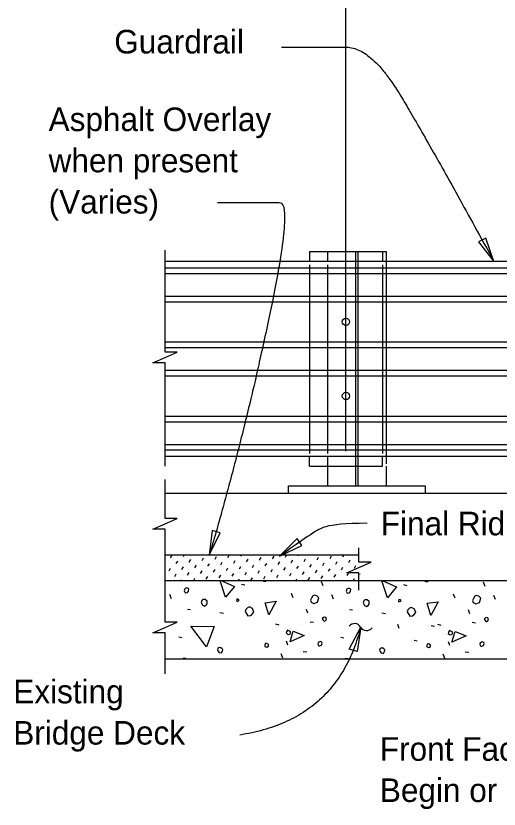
# Model space of a CAD drawing. Extents: x 21587 to 21656.3, y 56114 to 56157.2.
# Drawn here: x 21606.04 to 21610.17, y 56132.1 to 56138.88 of the extents above; entities that cross this region are included whole.
import ezdxf

# ---------------------------------------------------------------- set-up
doc = ezdxf.new("R2010")
doc.units = 0
for name, color, linetype in [('AdhocPoint_dp', 7, 'Continuous'), ('Border', 7, 'Continuous'), ('Patterning', 7, 'Continuous'), ('PlotBorder_dp', 7, 'Continuous'), ('SheetBorder_dp', 7, 'Continuous'), ('TextMisc', 7, 'Continuous')]:
    doc.layers.add(name, color=color, linetype=linetype)

msp = doc.modelspace()

# ---------------------------------------------------------------- linework, layer by layer
at = {"layer": 'AdhocPoint_dp'}
for p, q in [((21607.3117, 56134.8009), (21613.4854, 56134.8009)), ((21608.9696, 56134.2699), (21607.3116, 56134.2699)), ((21613.4854, 56134.0509), (21607.3117, 56134.0509)), ((21607.3117, 56133.3843), (21613.4854, 56133.3843))]:
    msp.add_line(p, q, dxfattribs=at)
at = {"layer": 'Border'}
for p, q in [((21608.7018, 56136.8635), (21609.2018, 56136.8635)), ((21608.7018, 56136.8635), (21608.7018, 56136.7802)), ((21619.5663, 56136.7801), (21607.3117, 56136.7801)), ((21607.3117, 56136.7246), (21619.5663, 56136.7246)), ((21607.3117, 56136.6764), (21619.5663, 56136.6764)), ((21607.3117, 56136.4835), (21619.5663, 56136.4835)), ((21607.3117, 56136.4353), (21619.5663, 56136.4353)), ((21607.3117, 56136.0914), (21619.5663, 56136.0914)), ((21607.3117, 56136.0431), (21619.5663, 56136.0431)), ((21607.3117, 56135.8503), (21619.5663, 56135.8503)), ((21607.3117, 56135.8022), (21619.5663, 56135.8022)), ((21607.3117, 56135.4582), (21619.5663, 56135.4582)), ((21607.3117, 56135.41), (21619.5663, 56135.41)), ((21607.3117, 56135.2172), (21619.5663, 56135.2172)), ((21607.3117, 56135.169), (21619.5663, 56135.169)), ((21619.5663, 56135.1134), (21607.3117, 56135.1134)), ((21608.7018, 56135.1135), (21608.7018, 56134.8635)), ((21609.2018, 56135.0302), (21609.2018, 56134.8635)), ((21608.3685, 56134.8635), (21609.5351, 56134.8635)), ((21608.3685, 56134.801), (21608.3685, 56134.8635)), ((21608.7018, 56134.8635), (21609.2018, 56134.8635)), ((21609.5351, 56134.8635), (21609.5351, 56134.801)), ((21608.3685, 56134.801), (21609.5351, 56134.801))]:
    msp.add_line(p, q, dxfattribs=at)
for centre in [(21608.858, 56136.2634), (21608.858, 56135.6303)]:
    msp.add_circle(centre, 0.0312, dxfattribs=at)
at = {"layer": 'Patterning'}
for p, q in [((21608.9414, 56134.8635), (21608.9414, 56136.8635)), ((21608.9622, 56134.8635), (21608.9622, 56136.8635)), ((21609.2018, 56136.8635), (21609.2018, 56135.0505)), ((21608.7018, 56136.7516), (21608.7018, 56135.1398))]:
    msp.add_line(p, q, dxfattribs=at)
at = {"layer": 'PlotBorder_dp'}
msp.add_line((21608.858, 56135.1577), (21608.858, 56143.2258), dxfattribs=at)
for points in [[(21610.1227, 56136.7797), (21610.0537, 56136.9793), (21609.9918, 56136.9455)], [(21607.6902, 56134.2707), (21607.7828, 56134.4606), (21607.7151, 56134.4805)], [(21608.2911, 56134.2633), (21608.4817, 56134.3543), (21608.4411, 56134.412)], [(21608.9843, 56133.6565), (21608.9539, 56133.4475), (21608.8867, 56133.4692)]]:
    msp.add_lwpolyline(points, close=True, dxfattribs=at)
for points in [[(21607.3117, 56135.0303), (21607.3117, 56135.9135), (21607.2084, 56135.9135), (21607.3117, 56135.9585), (21607.4151, 56136.0035), (21607.3117, 56136.0035), (21607.3117, 56136.8765)], [(21607.3117, 56134.0229), (21607.3117, 56134.493), (21607.2084, 56134.493), (21607.3117, 56134.538), (21607.4151, 56134.583), (21607.3117, 56134.583), (21607.3117, 56134.9175)], [(21608.9697, 56133.972), (21608.9697, 56134.1198), (21608.8664, 56134.1198), (21608.9697, 56134.1648), (21609.073, 56134.2098), (21608.9697, 56134.2098), (21608.9697, 56134.3343)], [(21607.3117, 56133.2578), (21607.3117, 56133.6084), (21607.2084, 56133.6084), (21607.3117, 56133.6534), (21607.4151, 56133.6984), (21607.3117, 56133.6984), (21607.3117, 56134.0229)]]:
    msp.add_lwpolyline(points, dxfattribs=at)
for centre, start, end in [((21608.9319, 56133.6269), 30.00813, 141.73535), ((21609.0352, 56133.6865), 210.00813, 321.73535)]:
    msp.add_arc(centre, 0.0596, start, end, dxfattribs=at)
for points, degree in [([(21608.3061, 56138.6093), (21608.6424, 56138.6093), (21609.0737, 56138.6093), (21609.5653, 56137.7986), (21610.1227, 56136.7797)], 2), ([(21607.7603, 56137.2827), (21608.1708, 56137.2827), (21608.4111, 56137.2827), (21607.9729, 56135.2323), (21607.6902, 56134.2708)], 2), ([(21609.0397, 56134.5436), (21608.8463, 56134.5415), (21608.6579, 56134.5211), (21608.5865, 56134.4713), (21608.2911, 56134.2634)], 3), ([(21608.9843, 56133.6565), (21608.7837, 56132.8621), (21607.9506, 56132.735)], 2)]:
    msp.add_open_spline(points, degree=degree, dxfattribs=at)
at = {"layer": 'TextMisc'}
for p, q in [((21608.5455, 56136.8635), (21609.1705, 56136.8635)), ((21608.5455, 56136.8635), (21608.5455, 56136.7802)), ((21609.1705, 56136.8635), (21609.1705, 56136.7802)), ((21608.5455, 56136.7516), (21608.5455, 56135.1398)), ((21609.1705, 56136.7516), (21609.1705, 56135.1398)), ((21608.5455, 56135.0302), (21608.5455, 56135.1135)), ((21609.1705, 56135.0302), (21609.1705, 56135.1135)), ((21608.5455, 56135.0302), (21609.1705, 56135.0302)), ((21607.3586, 56134.2474), (21607.3715, 56134.2698)), ((21607.4692, 56134.2604), (21607.4747, 56134.2699)), ((21607.6287, 56134.2245), (21607.6416, 56134.2469)), ((21607.7393, 56134.2375), (21607.7523, 56134.2599)), ((21607.8499, 56134.2504), (21607.8612, 56134.2699)), ((21607.9606, 56134.2634), (21607.9643, 56134.2699)), ((21608.0094, 56134.2146), (21608.0224, 56134.237)), ((21608.12, 56134.2275), (21608.133, 56134.2499)), ((21608.2307, 56134.2405), (21608.2436, 56134.2629)), ((21608.3413, 56134.2535), (21608.3508, 56134.2699)), ((21608.4519, 56134.2664), (21608.4539, 56134.2699)), ((21608.5008, 56134.2176), (21608.5137, 56134.24)), ((21608.6114, 56134.2306), (21608.6244, 56134.253)), ((21608.722, 56134.2435), (21608.735, 56134.2659)), ((21608.8327, 56134.2565), (21608.8404, 56134.2699)), ((21608.9433, 56134.2695), (21608.9436, 56134.2699)), ((21607.4074, 56134.1986), (21607.4204, 56134.221)), ((21607.4562, 56134.1498), (21607.4692, 56134.1722)), ((21607.518, 56134.2116), (21607.531, 56134.234)), ((21607.5669, 56134.1627), (21607.5798, 56134.1851)), ((21607.6775, 56134.1757), (21607.6905, 56134.1981)), ((21607.7881, 56134.1887), (21607.8011, 56134.211)), ((21607.8988, 56134.2016), (21607.9117, 56134.224)), ((21607.9476, 56134.1528), (21607.9606, 56134.1752)), ((21608.0582, 56134.1657), (21608.0712, 56134.1881)), ((21608.1689, 56134.1787), (21608.1818, 56134.2011)), ((21608.2795, 56134.1917), (21608.2925, 56134.2141)), ((21608.3901, 56134.2046), (21608.4031, 56134.227)), ((21608.439, 56134.1558), (21608.4519, 56134.1782)), ((21608.5496, 56134.1688), (21608.5626, 56134.1912)), ((21608.6602, 56134.1817), (21608.6732, 56134.2041)), ((21608.7709, 56134.1947), (21608.7838, 56134.2171)), ((21608.8197, 56134.1459), (21608.8327, 56134.1682)), ((21608.8815, 56134.2077), (21608.8945, 56134.23)), ((21608.9303, 56134.1588), (21608.9433, 56134.1812)), ((21607.3456, 56134.1368), (21607.3586, 56134.1592)), ((21607.3944, 56134.088), (21607.4074, 56134.1104)), ((21607.5051, 56134.1009), (21607.518, 56134.1233)), ((21607.6157, 56134.1139), (21607.6287, 56134.1363)), ((21607.7263, 56134.1269), (21607.7393, 56134.1492)), ((21607.7752, 56134.078), (21607.7881, 56134.1004)), ((21607.837, 56134.1398), (21607.8499, 56134.1622)), ((21607.8858, 56134.091), (21607.8988, 56134.1134)), ((21607.9964, 56134.1039), (21608.0094, 56134.1263)), ((21608.1071, 56134.1169), (21608.12, 56134.1393)), ((21608.2177, 56134.1299), (21608.2307, 56134.1523)), ((21608.2665, 56134.081), (21608.2795, 56134.1034)), ((21608.3283, 56134.1428), (21608.3413, 56134.1652)), ((21608.3772, 56134.094), (21608.3901, 56134.1164)), ((21608.4878, 56134.107), (21608.5008, 56134.1294)), ((21608.5984, 56134.1199), (21608.6114, 56134.1423)), ((21608.7091, 56134.1329), (21608.722, 56134.1553)), ((21608.7579, 56134.0841), (21608.7709, 56134.1065)), ((21608.8685, 56134.097), (21608.8815, 56134.1194)), ((21608.9792, 56134.11), (21608.9793, 56134.1102)), ((21607.4501, 56134.0509), (21607.4562, 56134.0615)), ((21607.5539, 56134.0521), (21607.5669, 56134.0745)), ((21607.6645, 56134.0651), (21607.6775, 56134.0874)), ((21607.8366, 56134.0509), (21607.837, 56134.0516)), ((21607.9397, 56134.0509), (21607.9476, 56134.0645)), ((21608.0453, 56134.0551), (21608.0582, 56134.0775)), ((21608.1559, 56134.0681), (21608.1689, 56134.0905)), ((21608.3262, 56134.0509), (21608.3283, 56134.0546)), ((21608.4293, 56134.0509), (21608.439, 56134.0676)), ((21608.5366, 56134.0581), (21608.5496, 56134.0805)), ((21608.6473, 56134.0711), (21608.6602, 56134.0935)), ((21608.6635, 56134.0079), (21608.6494, 56134.0432)), ((21608.8158, 56134.0509), (21608.8197, 56134.0576)), ((21608.919, 56134.0509), (21608.9303, 56134.0706)), ((21610.0482, 56134.0043), (21610.034, 56134.0397)), ((21607.9652, 56134.0238), (21607.9935, 56134.0167)), ((21609.3499, 56134.0203), (21609.3782, 56134.0132)), ((21607.3666, 56133.8989), (21607.3524, 56133.9343)), ((21608.4072, 56133.9071), (21608.393, 56133.9425)), ((21608.7513, 56133.8954), (21608.7371, 56133.9307)), ((21609.7919, 56133.9036), (21609.7777, 56133.9389)), ((21610.1359, 56133.8918), (21610.1218, 56133.9272)), ((21607.5045, 56133.8105), (21607.5292, 56133.807)), ((21607.7802, 56133.7822), (21607.8103, 56133.7769)), ((21608.5327, 56133.7745), (21608.5203, 56133.8081)), ((21608.8892, 56133.807), (21608.9139, 56133.8034)), ((21609.1649, 56133.7787), (21609.195, 56133.7734)), ((21609.9174, 56133.771), (21609.905, 56133.8046)), ((21608.5515, 56133.7027), (21608.5816, 56133.6974)), ((21609.9362, 56133.6991), (21609.9662, 56133.6938)), ((21608.2552, 56133.6844), (21608.2834, 56133.6773)), ((21609.3134, 56133.6443), (21609.301, 56133.6779)), ((21609.5874, 56133.6709), (21609.6157, 56133.6638)), ((21609.6398, 56133.6808), (21609.6681, 56133.6738)), ((21607.4302, 56133.5736), (21607.4567, 56133.5683)), ((21608.8149, 56133.5701), (21608.8414, 56133.5648)), ((21608.3612, 56133.5018), (21608.3488, 56133.5354)), ((21609.4407, 56133.5453), (21609.4672, 56133.54)), ((21609.7459, 56133.4982), (21609.7335, 56133.5318)), ((21608.3188, 56133.3922), (21608.3046, 56133.4275)), ((21608.4914, 56133.4481), (21608.5232, 56133.4446)), ((21609.7035, 56133.3886), (21609.6893, 56133.424)), ((21609.8761, 56133.4446), (21609.9079, 56133.4411))]:
    msp.add_line(p, q, dxfattribs=at)
for points in [[(21607.828, 56133.9113), (21607.7825, 56134.0509)], [(21607.7964, 56134.0509), (21607.9058, 56134.0032), (21607.828, 56133.9113)], [(21608.1516, 56134.0509), (21608.1526, 56134.0485), (21608.1502, 56134.0509)], [(21608.1526, 56134.0485), (21608.1738, 56134.0485), (21608.1762, 56134.0509)], [(21609.2127, 56133.9077), (21609.1661, 56134.0509)], [(21609.173, 56134.0509), (21609.2904, 56133.9997), (21609.2127, 56133.9077)], [(21609.5348, 56134.0509), (21609.5373, 56134.045), (21609.5338, 56134.0485)], [(21609.5373, 56134.045), (21609.5585, 56134.045), (21609.5644, 56134.0509)], [(21607.4762, 56133.9661), (21607.485, 56133.9502), (21607.5045, 56133.9519), (21607.5133, 56133.9643), (21607.5151, 56133.9838), (21607.5027, 56133.9891), (21607.4939, 56133.9908), (21607.4833, 56133.9873), (21607.4797, 56133.9838), (21607.4762, 56133.9661)], [(21608.8609, 56133.9625), (21608.8697, 56133.9466), (21608.8892, 56133.9484), (21608.898, 56133.9608), (21608.8998, 56133.9802), (21608.8874, 56133.9855), (21608.8785, 56133.9873), (21608.8679, 56133.9838), (21608.8644, 56133.9802), (21608.8609, 56133.9625)], [(21607.927, 56133.8759), (21607.9464, 56133.8848), (21607.9393, 56133.8918), (21607.927, 56133.8971), (21607.9217, 56133.8848), (21607.927, 56133.8759)], [(21608.561, 56133.87), (21608.584, 56133.8576), (21608.614, 56133.87), (21608.6264, 56133.9071), (21608.6087, 56133.9248), (21608.5857, 56133.9301), (21608.5751, 56133.923), (21608.5627, 56133.9036), (21608.5539, 56133.8877), (21608.561, 56133.87)], [(21609.9457, 56133.8665), (21609.9686, 56133.8541), (21609.9987, 56133.8665), (21610.0111, 56133.9036), (21609.9934, 56133.9213), (21609.9704, 56133.9266), (21609.9598, 56133.9195), (21609.9474, 56133.9), (21609.9386, 56133.8841), (21609.9457, 56133.8665)], [(21607.6211, 56133.8671), (21607.6318, 56133.8459), (21607.6494, 56133.8353), (21607.6636, 56133.8459), (21607.6706, 56133.8565), (21607.6706, 56133.8777), (21607.6547, 56133.8936), (21607.6353, 56133.8918), (21607.6265, 56133.883), (21607.6211, 56133.8671)], [(21608.2003, 56133.7604), (21608.1668, 56133.8647), (21608.2605, 56133.8771), (21608.2003, 56133.7604)], [(21609.0058, 56133.8635), (21609.0164, 56133.8423), (21609.0341, 56133.8317), (21609.0483, 56133.8423), (21609.0553, 56133.8529), (21609.0553, 56133.8742), (21609.0394, 56133.8901), (21609.02, 56133.8883), (21609.0111, 56133.8795), (21609.0058, 56133.8635)], [(21609.3116, 56133.8724), (21609.3311, 56133.8812), (21609.324, 56133.8883), (21609.3116, 56133.8936), (21609.3063, 56133.8812), (21609.3116, 56133.8724)], [(21609.585, 56133.7569), (21609.5514, 56133.8612), (21609.6451, 56133.8735), (21609.585, 56133.7569)], [(21607.9977, 56133.7911), (21608.0207, 56133.7539), (21608.0436, 56133.7557), (21608.0525, 56133.7646), (21608.0719, 56133.784), (21608.0596, 56133.814), (21608.0348, 56133.8282), (21608.0171, 56133.8211), (21608.003, 56133.807), (21607.9977, 56133.7911)], [(21609.3824, 56133.7875), (21609.4053, 56133.7504), (21609.4283, 56133.7522), (21609.4372, 56133.761), (21609.4566, 56133.7805), (21609.4442, 56133.8105), (21609.4195, 56133.8247), (21609.4018, 56133.8176), (21609.3877, 56133.8034), (21609.3824, 56133.7875)], [(21608.6629, 56133.7151), (21608.6735, 56133.7044), (21608.6841, 56133.7115), (21608.6912, 56133.7221), (21608.6876, 56133.7398), (21608.6788, 56133.7416), (21608.6664, 56133.7398), (21608.6558, 56133.7292), (21608.6629, 56133.7151)], [(21610.0476, 56133.7115), (21610.0582, 56133.7009), (21610.0688, 56133.708), (21610.0758, 56133.7186), (21610.0723, 56133.7363), (21610.0635, 56133.738), (21610.0511, 56133.7363), (21610.0405, 56133.7257), (21610.0476, 56133.7115)], [(21607.6653, 56133.487), (21607.531, 56133.6638), (21607.7307, 56133.662), (21607.6653, 56133.487)], [(21608.3577, 56133.596), (21608.3701, 56133.5942), (21608.3824, 56133.5995), (21608.386, 56133.6101), (21608.3807, 56133.619), (21608.3701, 56133.626), (21608.3577, 56133.6313), (21608.3506, 56133.6172), (21608.3471, 56133.6066), (21608.3577, 56133.596)], [(21609.7424, 56133.5925), (21609.7547, 56133.5907), (21609.7671, 56133.596), (21609.7706, 56133.6066), (21609.7653, 56133.6154), (21609.7547, 56133.6225), (21609.7424, 56133.6278), (21609.7353, 56133.6137), (21609.7318, 56133.6031), (21609.7424, 56133.5925)], [(21608.38, 56133.5312), (21608.4083, 56133.6231), (21608.502, 56133.586), (21608.38, 56133.5312)], [(21609.7647, 56133.5277), (21609.793, 56133.6196), (21609.8867, 56133.5825), (21609.7647, 56133.5277)], [(21608.1639, 56133.4905), (21608.1833, 56133.4852), (21608.1957, 56133.4941), (21608.1974, 56133.5065), (21608.1939, 56133.51), (21608.1798, 56133.5171), (21608.1674, 56133.5153), (21608.1656, 56133.5029), (21608.1639, 56133.4905)], [(21608.6275, 56133.4959), (21608.6346, 56133.4959), (21608.6487, 56133.5029), (21608.654, 56133.5188), (21608.6523, 56133.5277), (21608.6381, 56133.5347), (21608.6205, 56133.5241), (21608.6169, 56133.5135), (21608.6205, 56133.5029), (21608.6275, 56133.4959)], [(21609.5485, 56133.487), (21609.568, 56133.4817), (21609.5803, 56133.4905), (21609.5821, 56133.5029), (21609.5786, 56133.5065), (21609.5644, 56133.5135), (21609.5521, 56133.5118), (21609.5503, 56133.4994), (21609.5485, 56133.487)], [(21610.0122, 56133.4923), (21610.0193, 56133.4923), (21610.0334, 56133.4994), (21610.0387, 56133.5153), (21610.0369, 56133.5241), (21610.0228, 56133.5312), (21610.0051, 56133.5206), (21610.0016, 56133.51), (21610.0051, 56133.4994), (21610.0122, 56133.4923)], [(21607.7643, 56133.4552), (21607.7732, 56133.4393), (21607.7944, 56133.4357), (21607.8032, 56133.4517), (21607.8068, 56133.4658), (21607.7979, 56133.4746), (21607.782, 56133.4835), (21607.7661, 56133.4782), (21607.7608, 56133.4623), (21607.7643, 56133.4552)], [(21609.149, 56133.4517), (21609.1579, 56133.4357), (21609.1791, 56133.4322), (21609.1879, 56133.4481), (21609.1914, 56133.4623), (21609.1826, 56133.4711), (21609.1667, 56133.4799), (21609.1508, 56133.4746), (21609.1455, 56133.4587), (21609.149, 56133.4517)], [(21607.4896, 56133.3843), (21607.4886, 56133.388), (21607.4656, 56133.3898), (21607.4637, 56133.3843)], [(21608.8733, 56133.3843), (21608.8732, 56133.3845), (21608.8503, 56133.3862), (21608.8496, 56133.3843)]]:
    msp.add_lwpolyline(points, dxfattribs=at)

# ---------------------------------------------------------------- texts
at = {"layer": 'PlotBorder_dp'}
for s, p in [('Guardrail', (21606.8775, 56138.5552)), ('Asphalt Overlay', (21606.3166, 56137.8923)), ('when present', (21606.3166, 56137.5403)), ('(Varies)', (21606.3166, 56137.1883)), ('Existing ', (21606.0143, 56133.0052)), ('Bridge Deck', (21606.0143, 56132.6532)), ('Front Face of Backwall &', (21609.1479, 56132.5148)), ('Begin or End Bridge', (21609.1479, 56132.1628))]:
    msp.add_text(s, height=0.2016, dxfattribs=at).set_placement(p)
at = {"layer": 'SheetBorder_dp'}
msp.add_text('Final Riding Surface', height=0.2016, dxfattribs=at).set_placement((21609.1559, 56134.44))

doc.saveas('drawing.dxf')
